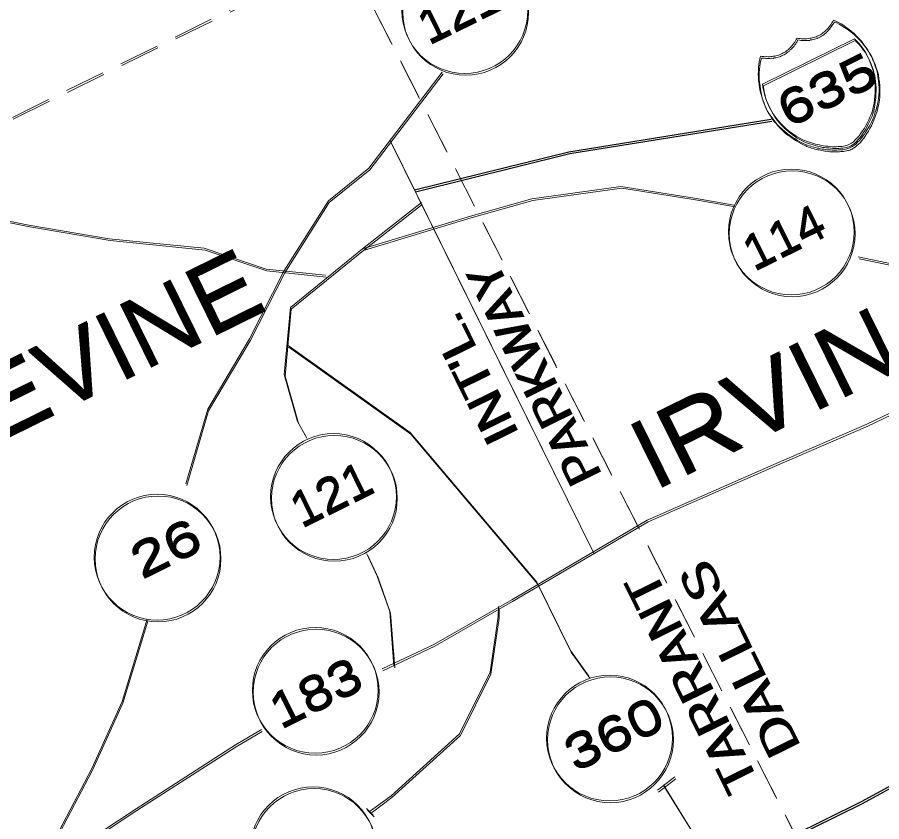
# Model space of a CAD drawing. Extents: x 2356606 to 2371222, y 6973096 to 6982644.
# Drawn here: x 2357309.1 to 2357437.7, y 6973747.7 to 6973867.4 of the extents above; entities that cross this region are included whole.
import ezdxf

# ---------------------------------------------------------------- set-up
doc = ezdxf.new("R2010")
doc.units = 0
doc.header["$LTSCALE"] = 2
doc.linetypes.add('MEDIUM_DASHED', pattern=[4.5, 3, -1.5])
doc.layers.add('62', color=7, linetype='Continuous', lineweight=13)
doc.layers.add('63', color=7, linetype='Continuous', lineweight=13)

msp = doc.modelspace()

# ---------------------------------------------------------------- linework, layer by layer
at = {"layer": '62', "linetype": 'MEDIUM_DASHED'}
for p, q in [((2357443, 6973918.637), (2357041.025, 6973720.25)), ((2357358.049, 6973876.711), (2357485.75, 6973626.399))]:
    msp.add_line(p, q, dxfattribs=at)
at = {"layer": '62'}
for p, q in [((2357394.922, 6973787.559), (2357364.687, 6973848.822)), ((2357410.008, 6973840.223), (2357415.92, 6973839.177)), ((2357360.597, 6973832.702), (2357369.36, 6973839.56)), ((2357456.191, 6973826.984), (2357434.377, 6973831.474)), ((2357346.242, 6973829.655), (2357355.071, 6973828.746)), ((2357337.561, 6973808.811), (2357334.311, 6973797.696)), ((2357350.935, 6973806.979), (2357352.173, 6973804.778)), ((2357362.79, 6973783.975), (2357361.238, 6973787.274)), ((2357386.516, 6973783.085), (2357391.537, 6973772.916)), ((2357380.793, 6973777.951), (2357380.822, 6973779.421)), ((2357324.805, 6973765.304), (2357328.532, 6973777.531)), ((2357371.211, 6973773.776), (2357363.494, 6973770.143)), ((2357391.537, 6973772.916), (2357394.271, 6973769.048)), ((2357341.679, 6973758.824), (2357345.543, 6973761.108)), ((2357404.5, 6973752.087), (2357407.087, 6973754.067)), ((2357411.935, 6973742.308), (2357405.378, 6973752.897)), ((2357364.834, 6973751.259), (2357361.935, 6973749.099)), ((2357361.191, 6973749.385), (2357362.192, 6973748.374)), ((2357361.652, 6973748.908), (2357361.935, 6973749.099))]:
    msp.add_line(p, q, dxfattribs=at)
for points in [[(2357426.144, 6973863.972), (2357426.353, 6973863.95), (2357426.574, 6973863.959), (2357426.746, 6973863.968), (2357426.989, 6973863.987), (2357427.16, 6973864.047), (2357427.361, 6973864.046), (2357427.532, 6973864.106), (2357427.734, 6973864.154), (2357427.914, 6973864.195), (2357428.108, 6973864.264), (2357428.269, 6973864.344), (2357428.448, 6973864.432), (2357428.61, 6973864.511), (2357428.793, 6973864.602), (2357428.966, 6973864.711), (2357429.106, 6973864.831), (2357429.228, 6973864.941), (2357429.398, 6973865.052), (2357429.54, 6973865.222), (2357429.691, 6973865.321), (2357429.833, 6973865.491), (2357429.964, 6973865.632), (2357430.085, 6973865.792), (2357430.219, 6973865.983), (2357430.321, 6973866.133), (2357430.452, 6973866.325), (2357430.584, 6973866.513), (2357430.685, 6973866.715), (2357431.056, 6973866.57), (2357431.428, 6973866.379), (2357431.808, 6973866.165), (2357432.21, 6973865.911), (2357432.592, 6973865.648), (2357432.982, 6973865.365), (2357433.384, 6973865.061), (2357433.745, 6973864.737), (2357434.135, 6973864.352), (2357434.484, 6973863.999), (2357434.835, 6973863.593), (2357435.165, 6973863.178), (2357435.476, 6973862.756), (2357435.783, 6973862.332), (2357436.023, 6973861.896), (2357436.293, 6973861.453), (2357436.501, 6973860.927), (2357436.741, 6973860.396), (2357436.898, 6973859.871), (2357437.097, 6973859.367), (2357437.236, 6973858.833), (2357437.312, 6973858.268), (2357437.392, 6973857.754), (2357437.459, 6973857.211), (2357437.475, 6973856.667), (2357437.462, 6973856.134), (2357437.449, 6973855.599), (2357437.387, 6973855.066), (2357437.294, 6973854.494), (2357437.179, 6973853.96), (2357437.037, 6973853.437), (2357436.862, 6973852.875), (2357436.732, 6973852.484), (2357436.578, 6973852.082), (2357436.384, 6973851.661), (2357436.201, 6973851.269), (2357435.987, 6973850.885), (2357435.764, 6973850.476), (2357435.52, 6973850.104), (2357435.296, 6973849.743), (2357435.074, 6973849.435), (2357434.81, 6973849.102), (2357434.559, 6973848.801), (2357434.284, 6973848.541), (2357434.043, 6973848.32), (2357433.799, 6973848.101), (2357433.535, 6973847.921), (2357433.295, 6973847.801)], [(2357433.295, 6973847.801), (2357433.132, 6973847.721), (2357432.99, 6973847.652), (2357432.81, 6973847.61), (2357432.659, 6973847.563), (2357432.477, 6973847.525), (2357432.296, 6973847.484), (2357432.064, 6973847.445), (2357431.851, 6973847.416), (2357431.653, 6973847.419), (2357431.43, 6973847.409), (2357431.189, 6973847.388), (2357430.969, 6973847.38), (2357430.714, 6973847.382), (2357430.513, 6973847.383), (2357430.253, 6973847.405), (2357430, 6973847.406), (2357429.762, 6973847.437), (2357429.49, 6973847.477), (2357429.248, 6973847.511), (2357429.005, 6973847.542), (2357428.757, 6973847.593), (2357428.493, 6973847.666), (2357428.253, 6973847.696), (2357428.02, 6973847.758), (2357427.77, 6973847.808), (2357427.54, 6973847.872), (2357427.297, 6973847.952), (2357427.075, 6973848.044), (2357426.825, 6973848.096), (2357426.614, 6973848.166), (2357426.434, 6973848.278), (2357426.184, 6973848.382), (2357425.781, 6973848.583), (2357425.339, 6973848.82), (2357424.927, 6973849.093), (2357424.536, 6973849.327), (2357424.143, 6973849.612), (2357423.733, 6973849.886), (2357423.382, 6973850.191), (2357423.012, 6973850.534), (2357422.649, 6973850.857), (2357422.32, 6973851.218), (2357422.012, 6973851.594), (2357421.7, 6973851.968), (2357421.402, 6973852.372), (2357421.122, 6973852.786), (2357420.842, 6973853.25), (2357420.612, 6973853.715), (2357420.403, 6973854.189), (2357420.225, 6973854.653), (2357420.057, 6973855.147), (2357419.909, 6973855.651), (2357419.78, 6973856.165), (2357419.671, 6973856.688), (2357419.624, 6973857.19), (2357419.536, 6973857.726), (2357419.522, 6973858.22), (2357419.502, 6973858.712), (2357419.516, 6973859.195), (2357419.538, 6973859.657), (2357419.6, 6973860.14), (2357419.644, 6973860.562), (2357419.737, 6973860.984), (2357419.83, 6973861.356), (2357420.049, 6973861.314), (2357420.303, 6973861.315), (2357420.513, 6973861.292), (2357420.713, 6973861.294), (2357420.944, 6973861.281), (2357421.147, 6973861.281), (2357421.358, 6973861.309), (2357421.56, 6973861.308), (2357421.732, 6973861.366), (2357421.953, 6973861.375), (2357422.123, 6973861.437), (2357422.324, 6973861.485), (2357422.525, 6973861.535), (2357422.677, 6973861.583), (2357422.838, 6973861.664), (2357423.041, 6973861.764), (2357423.202, 6973861.843), (2357423.364, 6973861.922), (2357423.535, 6973862.033), (2357423.679, 6973862.153), (2357423.82, 6973862.274), (2357423.99, 6973862.38), (2357424.131, 6973862.551), (2357424.282, 6973862.652), (2357424.404, 6973862.812), (2357424.538, 6973862.952), (2357424.699, 6973863.132), (2357424.81, 6973863.314), (2357424.931, 6973863.474), (2357425.045, 6973863.655), (2357425.156, 6973863.837), (2357425.276, 6973864.045), (2357425.497, 6973864.005), (2357425.708, 6973863.983), (2357425.939, 6973863.971), (2357426.144, 6973863.972)], [(2357348.897, 6973829.361), (2357355.513, 6973839.852), (2357361.543, 6973844.711), (2357372.468, 6973858.985)], [(2357371.211, 6973773.776), (2357382.807, 6973780.427), (2357402.976, 6973792.286), (2357422.585, 6973800.911), (2357435.675, 6973806.569), (2357451.93, 6973814.364), (2357460.097, 6973821.157), (2357467.581, 6973832.831), (2357476.49, 6973844.732), (2357479.572, 6973847.534)], [(2357376.643, 6973837.56), (2357385.815, 6973840.13), (2357399.038, 6973841.963), (2357410.008, 6973840.223)], [(2357080.613, 6973783.875), (2357087.936, 6973792.988), (2357099.933, 6973800.965), (2357117.628, 6973801.466), (2357127.853, 6973805.459), (2357143.158, 6973805.208), (2357153.653, 6973805.143), (2357162.234, 6973806.017), (2357173.377, 6973809.108), (2357182.038, 6973812.405), (2357193.134, 6973817.38), (2357205.647, 6973824.158), (2357222.908, 6973830.116), (2357233.839, 6973834.608), (2357246.593, 6973839.121), (2357262.801, 6973839.788), (2357278.346, 6973840.111), (2357292.838, 6973839.837), (2357310.932, 6973836.221), (2357322.909, 6973834.174), (2357337.032, 6973832.764), (2357346.242, 6973829.655)], [(2357349.867, 6973823.943), (2357360.597, 6973832.702), (2357376.643, 6973837.56)], [(2357348.897, 6973829.361), (2357343.762, 6973819.275), (2357337.561, 6973808.811)], [(2357350.935, 6973806.979), (2357348.958, 6973813.986), (2357349.867, 6973823.943)], [(2357386.516, 6973783.085), (2357367.672, 6973805.352), (2357349.514, 6973818.3)], [(2357365.268, 6973770.567), (2357364.637, 6973778.71), (2357362.79, 6973783.975)], [(2357364.834, 6973751.259), (2357375.028, 6973760.503), (2357379.574, 6973769.647), (2357380.793, 6973777.951)], [(2357324.805, 6973765.304), (2357320.284, 6973755.34), (2357311.656, 6973738.864)], [(2357311.295, 6973738.987), (2357326.895, 6973749.32), (2357341.679, 6973758.824)]]:
    msp.add_lwpolyline(points, dxfattribs=at)
msp.add_lwpolyline([(2357433.8, 6973863.961), (2357420.139, 6973857.219), (2357420.158, 6973856.976), (2357420.197, 6973856.695), (2357420.255, 6973856.373), (2357420.363, 6973855.951), (2357420.461, 6973855.495), (2357420.599, 6973855.013), (2357420.828, 6973854.499), (2357421.079, 6973853.945), (2357421.376, 6973853.388), (2357421.674, 6973852.833), (2357422.034, 6973852.308), (2357422.424, 6973851.824), (2357422.825, 6973851.37), (2357423.235, 6973850.945), (2357423.697, 6973850.52), (2357424.158, 6973850.145), (2357424.629, 6973849.801), (2357425.132, 6973849.446), (2357425.673, 6973849.16), (2357426.215, 6973848.875), (2357426.808, 6973848.641), (2357427.401, 6973848.456), (2357427.992, 6973848.27), (2357428.606, 6973848.147), (2357428.908, 6973848.046), (2357429.22, 6973848.024), (2357429.52, 6973847.972), (2357429.853, 6973847.96), (2357430.144, 6973847.927), (2357430.466, 6973847.886), (2357430.767, 6973847.885), (2357431.07, 6973847.882), (2357431.361, 6973847.902), (2357431.633, 6973847.911), (2357431.925, 6973847.929), (2357432.177, 6973847.979), (2357432.431, 6973848.026), (2357432.651, 6973848.086), (2357432.871, 6973848.145), (2357433.074, 6973848.245), (2357433.348, 6973848.405), (2357433.663, 6973848.634), (2357433.935, 6973848.895), (2357434.228, 6973849.216), (2357434.51, 6973849.506), (2357434.775, 6973849.887), (2357435.018, 6973850.258), (2357435.283, 6973850.638), (2357435.526, 6973851.059), (2357435.738, 6973851.491), (2357435.942, 6973851.892), (2357436.113, 6973852.304), (2357436.299, 6973852.696), (2357436.431, 6973853.089), (2357436.554, 6973853.449), (2357436.595, 6973853.772), (2357436.721, 6973854.336), (2357436.771, 6973854.889), (2357436.846, 6973855.402), (2357436.878, 6973855.947), (2357436.9, 6973856.459), (2357436.894, 6973856.932), (2357436.866, 6973857.396), (2357436.808, 6973857.87), (2357436.748, 6973858.339), (2357436.692, 6973858.765), (2357436.573, 6973859.209), (2357436.446, 6973859.621), (2357436.315, 6973860.035), (2357436.167, 6973860.439), (2357435.997, 6973860.832), (2357435.809, 6973861.215), (2357435.542, 6973861.759), (2357435.252, 6973862.243), (2357434.95, 6973862.646), (2357434.692, 6973863.021), (2357434.4, 6973863.355), (2357434.161, 6973863.586), (2357433.962, 6973863.789)], close=True, dxfattribs=at)
at = {"layer": '62', "lineweight": 25}
for points in [[(2357421.398, 6973851.92), (2357391.316, 6973847.084), (2357368.351, 6973841.397)], [(2357505.855, 6973794.281), (2357494.638, 6973787.314), (2357477.945, 6973775.941), (2357457.618, 6973762.773), (2357434.819, 6973750.341), (2357408.769, 6973737.485), (2357380.527, 6973722.566), (2357364.72, 6973713.512)]]:
    msp.add_lwpolyline(points, dxfattribs=at)
at = {"layer": '62'}
for centre in [(2357375.818, 6973868.156), (2357424.414, 6973835.192), (2357356.277, 6973795.807), (2357330.031, 6973786.786), (2357353.563, 6973766.958), (2357397.363, 6973759.862), (2357353.248, 6973743.227)]:
    msp.add_circle(centre, 9.364, dxfattribs=at)
at = {"layer": '63', "linetype": 'MEDIUM_DASHED'}
for p, q in [((2357442.87, 6973918.9), (2357040.895, 6973720.513)), ((2357357.919, 6973876.974), (2357485.62, 6973626.662))]:
    msp.add_line(p, q, dxfattribs=at)
at = {"layer": '63'}
for p, q in [((2357394.792, 6973787.822), (2357364.557, 6973849.085)), ((2357409.878, 6973840.486), (2357415.79, 6973839.44)), ((2357360.467, 6973832.965), (2357369.23, 6973839.823)), ((2357456.061, 6973827.247), (2357434.247, 6973831.737)), ((2357346.112, 6973829.918), (2357354.941, 6973829.009)), ((2357337.431, 6973809.074), (2357334.181, 6973797.959)), ((2357350.805, 6973807.242), (2357352.043, 6973805.041)), ((2357362.66, 6973784.238), (2357361.108, 6973787.537)), ((2357386.386, 6973783.348), (2357391.407, 6973773.179)), ((2357380.663, 6973778.214), (2357380.692, 6973779.684)), ((2357324.675, 6973765.567), (2357328.402, 6973777.794)), ((2357371.081, 6973774.039), (2357363.364, 6973770.406)), ((2357391.407, 6973773.179), (2357394.141, 6973769.311)), ((2357341.549, 6973759.087), (2357345.413, 6973761.371)), ((2357404.37, 6973752.35), (2357406.957, 6973754.33)), ((2357411.805, 6973742.571), (2357405.248, 6973753.16)), ((2357364.704, 6973751.522), (2357361.805, 6973749.362)), ((2357361.061, 6973749.648), (2357362.062, 6973748.637)), ((2357361.522, 6973749.171), (2357361.805, 6973749.362))]:
    msp.add_line(p, q, dxfattribs=at)
for points in [[(2357426.014, 6973864.235), (2357426.223, 6973864.213), (2357426.444, 6973864.222), (2357426.616, 6973864.231), (2357426.859, 6973864.25), (2357427.03, 6973864.31), (2357427.231, 6973864.309), (2357427.402, 6973864.369), (2357427.604, 6973864.417), (2357427.784, 6973864.458), (2357427.978, 6973864.527), (2357428.139, 6973864.607), (2357428.318, 6973864.695), (2357428.48, 6973864.774), (2357428.663, 6973864.865), (2357428.836, 6973864.974), (2357428.976, 6973865.094), (2357429.098, 6973865.204), (2357429.268, 6973865.315), (2357429.41, 6973865.485), (2357429.561, 6973865.584), (2357429.703, 6973865.754), (2357429.834, 6973865.895), (2357429.955, 6973866.055), (2357430.089, 6973866.246), (2357430.191, 6973866.396), (2357430.322, 6973866.588), (2357430.454, 6973866.776), (2357430.555, 6973866.978), (2357430.926, 6973866.833), (2357431.298, 6973866.642), (2357431.678, 6973866.428), (2357432.08, 6973866.174), (2357432.462, 6973865.911), (2357432.852, 6973865.628), (2357433.254, 6973865.324), (2357433.615, 6973865), (2357434.005, 6973864.615), (2357434.354, 6973864.262), (2357434.705, 6973863.856), (2357435.035, 6973863.441), (2357435.346, 6973863.019), (2357435.653, 6973862.595), (2357435.893, 6973862.159), (2357436.163, 6973861.716), (2357436.371, 6973861.19), (2357436.611, 6973860.659), (2357436.768, 6973860.134), (2357436.967, 6973859.63), (2357437.106, 6973859.096), (2357437.182, 6973858.531), (2357437.262, 6973858.017), (2357437.329, 6973857.474), (2357437.345, 6973856.93), (2357437.332, 6973856.397), (2357437.319, 6973855.862), (2357437.257, 6973855.329), (2357437.164, 6973854.757), (2357437.049, 6973854.223), (2357436.907, 6973853.7), (2357436.732, 6973853.138), (2357436.602, 6973852.747), (2357436.448, 6973852.345), (2357436.254, 6973851.924), (2357436.071, 6973851.532), (2357435.857, 6973851.148), (2357435.634, 6973850.739), (2357435.39, 6973850.367), (2357435.166, 6973850.006), (2357434.944, 6973849.698), (2357434.68, 6973849.365), (2357434.429, 6973849.064), (2357434.154, 6973848.804), (2357433.913, 6973848.583), (2357433.669, 6973848.364), (2357433.405, 6973848.184), (2357433.165, 6973848.064)], [(2357433.165, 6973848.064), (2357433.002, 6973847.984), (2357432.86, 6973847.915), (2357432.68, 6973847.873), (2357432.529, 6973847.826), (2357432.347, 6973847.788), (2357432.166, 6973847.747), (2357431.934, 6973847.708), (2357431.721, 6973847.679), (2357431.523, 6973847.682), (2357431.3, 6973847.672), (2357431.059, 6973847.651), (2357430.839, 6973847.643), (2357430.584, 6973847.645), (2357430.383, 6973847.646), (2357430.123, 6973847.668), (2357429.87, 6973847.669), (2357429.632, 6973847.7), (2357429.36, 6973847.74), (2357429.118, 6973847.774), (2357428.875, 6973847.805), (2357428.627, 6973847.856), (2357428.363, 6973847.929), (2357428.123, 6973847.959), (2357427.89, 6973848.021), (2357427.64, 6973848.071), (2357427.41, 6973848.135), (2357427.167, 6973848.215), (2357426.945, 6973848.307), (2357426.695, 6973848.359), (2357426.484, 6973848.429), (2357426.304, 6973848.541), (2357426.054, 6973848.645), (2357425.651, 6973848.846), (2357425.209, 6973849.083), (2357424.797, 6973849.356), (2357424.406, 6973849.59), (2357424.013, 6973849.875), (2357423.603, 6973850.149), (2357423.252, 6973850.454), (2357422.882, 6973850.797), (2357422.519, 6973851.12), (2357422.19, 6973851.481), (2357421.882, 6973851.857), (2357421.57, 6973852.231), (2357421.272, 6973852.635), (2357420.992, 6973853.049), (2357420.712, 6973853.513), (2357420.482, 6973853.978), (2357420.273, 6973854.452), (2357420.095, 6973854.916), (2357419.927, 6973855.41), (2357419.779, 6973855.914), (2357419.65, 6973856.428), (2357419.541, 6973856.951), (2357419.494, 6973857.453), (2357419.406, 6973857.989), (2357419.392, 6973858.483), (2357419.372, 6973858.975), (2357419.386, 6973859.458), (2357419.408, 6973859.92), (2357419.47, 6973860.403), (2357419.514, 6973860.825), (2357419.607, 6973861.247), (2357419.7, 6973861.619), (2357419.919, 6973861.577), (2357420.173, 6973861.578), (2357420.383, 6973861.555), (2357420.583, 6973861.557), (2357420.814, 6973861.544), (2357421.017, 6973861.544), (2357421.228, 6973861.572), (2357421.43, 6973861.571), (2357421.602, 6973861.629), (2357421.823, 6973861.638), (2357421.993, 6973861.7), (2357422.194, 6973861.748), (2357422.395, 6973861.798), (2357422.547, 6973861.846), (2357422.708, 6973861.927), (2357422.911, 6973862.027), (2357423.072, 6973862.106), (2357423.234, 6973862.185), (2357423.405, 6973862.296), (2357423.549, 6973862.416), (2357423.69, 6973862.537), (2357423.86, 6973862.643), (2357424.001, 6973862.814), (2357424.152, 6973862.915), (2357424.274, 6973863.075), (2357424.408, 6973863.215), (2357424.569, 6973863.395), (2357424.68, 6973863.577), (2357424.801, 6973863.737), (2357424.915, 6973863.918), (2357425.026, 6973864.1), (2357425.146, 6973864.308), (2357425.367, 6973864.268), (2357425.578, 6973864.246), (2357425.809, 6973864.234), (2357426.014, 6973864.235)], [(2357348.767, 6973829.624), (2357355.383, 6973840.115), (2357361.413, 6973844.974), (2357372.338, 6973859.248)], [(2357371.081, 6973774.039), (2357382.677, 6973780.69), (2357402.846, 6973792.549), (2357422.455, 6973801.174), (2357435.545, 6973806.832), (2357451.8, 6973814.627), (2357459.967, 6973821.42), (2357467.451, 6973833.094), (2357476.36, 6973844.995), (2357479.442, 6973847.797)], [(2357376.513, 6973837.823), (2357385.685, 6973840.393), (2357398.908, 6973842.226), (2357409.878, 6973840.486)], [(2357080.483, 6973784.138), (2357087.806, 6973793.251), (2357099.803, 6973801.228), (2357117.498, 6973801.729), (2357127.723, 6973805.722), (2357143.028, 6973805.471), (2357153.523, 6973805.406), (2357162.104, 6973806.28), (2357173.247, 6973809.371), (2357181.908, 6973812.668), (2357193.004, 6973817.643), (2357205.517, 6973824.421), (2357222.778, 6973830.379), (2357233.709, 6973834.871), (2357246.463, 6973839.384), (2357262.671, 6973840.051), (2357278.216, 6973840.374), (2357292.708, 6973840.1), (2357310.802, 6973836.484), (2357322.779, 6973834.437), (2357336.902, 6973833.027), (2357346.112, 6973829.918)], [(2357349.737, 6973824.206), (2357360.467, 6973832.965), (2357376.513, 6973837.823)], [(2357348.767, 6973829.624), (2357343.632, 6973819.538), (2357337.431, 6973809.074)], [(2357350.805, 6973807.242), (2357348.828, 6973814.249), (2357349.737, 6973824.206)], [(2357386.386, 6973783.348), (2357367.542, 6973805.615), (2357349.384, 6973818.563)], [(2357365.138, 6973770.83), (2357364.507, 6973778.973), (2357362.66, 6973784.238)], [(2357364.704, 6973751.522), (2357374.898, 6973760.766), (2357379.444, 6973769.91), (2357380.663, 6973778.214)], [(2357324.675, 6973765.567), (2357320.154, 6973755.603), (2357311.526, 6973739.127)], [(2357311.165, 6973739.25), (2357326.765, 6973749.583), (2357341.549, 6973759.087)]]:
    msp.add_lwpolyline(points, dxfattribs=at)
msp.add_lwpolyline([(2357433.67, 6973864.224), (2357420.009, 6973857.482), (2357420.028, 6973857.239), (2357420.067, 6973856.958), (2357420.125, 6973856.636), (2357420.233, 6973856.214), (2357420.331, 6973855.758), (2357420.469, 6973855.276), (2357420.698, 6973854.762), (2357420.949, 6973854.208), (2357421.246, 6973853.651), (2357421.544, 6973853.096), (2357421.904, 6973852.571), (2357422.294, 6973852.087), (2357422.695, 6973851.633), (2357423.105, 6973851.208), (2357423.567, 6973850.783), (2357424.028, 6973850.408), (2357424.499, 6973850.064), (2357425.002, 6973849.709), (2357425.543, 6973849.423), (2357426.085, 6973849.138), (2357426.678, 6973848.904), (2357427.271, 6973848.719), (2357427.862, 6973848.533), (2357428.476, 6973848.41), (2357428.778, 6973848.309), (2357429.09, 6973848.287), (2357429.39, 6973848.235), (2357429.723, 6973848.223), (2357430.014, 6973848.19), (2357430.336, 6973848.149), (2357430.637, 6973848.148), (2357430.94, 6973848.145), (2357431.231, 6973848.165), (2357431.503, 6973848.174), (2357431.795, 6973848.192), (2357432.047, 6973848.242), (2357432.301, 6973848.289), (2357432.521, 6973848.349), (2357432.741, 6973848.408), (2357432.944, 6973848.508), (2357433.218, 6973848.668), (2357433.533, 6973848.897), (2357433.805, 6973849.158), (2357434.098, 6973849.479), (2357434.38, 6973849.769), (2357434.645, 6973850.15), (2357434.888, 6973850.521), (2357435.153, 6973850.901), (2357435.396, 6973851.322), (2357435.608, 6973851.754), (2357435.812, 6973852.155), (2357435.983, 6973852.567), (2357436.169, 6973852.959), (2357436.301, 6973853.352), (2357436.424, 6973853.712), (2357436.465, 6973854.035), (2357436.591, 6973854.599), (2357436.641, 6973855.152), (2357436.716, 6973855.665), (2357436.748, 6973856.21), (2357436.77, 6973856.722), (2357436.764, 6973857.195), (2357436.736, 6973857.659), (2357436.678, 6973858.133), (2357436.618, 6973858.602), (2357436.562, 6973859.028), (2357436.443, 6973859.472), (2357436.316, 6973859.884), (2357436.185, 6973860.298), (2357436.037, 6973860.702), (2357435.867, 6973861.095), (2357435.679, 6973861.478), (2357435.412, 6973862.022), (2357435.122, 6973862.506), (2357434.82, 6973862.909), (2357434.562, 6973863.284), (2357434.27, 6973863.618), (2357434.031, 6973863.849), (2357433.832, 6973864.052)], close=True, dxfattribs=at)
at = {"layer": '63', "lineweight": 25}
for points in [[(2357421.268, 6973852.183), (2357391.186, 6973847.347), (2357368.221, 6973841.66)], [(2357505.725, 6973794.544), (2357494.508, 6973787.577), (2357477.815, 6973776.204), (2357457.488, 6973763.036), (2357434.689, 6973750.604), (2357408.639, 6973737.748), (2357380.397, 6973722.829), (2357364.59, 6973713.775)]]:
    msp.add_lwpolyline(points, dxfattribs=at)
at = {"layer": '63'}
for centre in [(2357375.688, 6973868.419), (2357424.284, 6973835.455), (2357356.147, 6973796.07), (2357329.901, 6973787.049), (2357353.433, 6973767.222), (2357397.233, 6973760.125), (2357353.118, 6973743.49)]:
    msp.add_circle(centre, 9.364, dxfattribs=at)

# ---------------------------------------------------------------- texts
at = {"layer": '62'}
for s, height, rotation, width, p in [('121', 5.099, 26.268, 1.1, (2357370.364, 6973863.145)), ('635', 5.099, 26.268, 1.35, (2357423.899, 6973850.821)), ('114', 5.099, 26.268, 1.1, (2357418.759, 6973829.463)), ('GRAPEVINE', 10.21, 26.268, 1.1, (2357268.029, 6973785.16)), ('PARKWAY', 5.099, 116.268, 1.05, (2357396.22, 6973799.27)), ('IRVING', 10.21, 26.268, 1.15, (2357403.785, 6973796.752)), ("INT'L.", 5.099, 116.268, 1.15, (2357383.906, 6973805.361)), ('121', 5.099, 26.268, 1.1, (2357351.408, 6973791.23)), ('26', 5.099, 26.268, 1.4, (2357327.617, 6973783.604)), ('DALLAS', 5.099, 116.268, 1.2, (2357425.839, 6973758.781)), ('TARRANT', 5.099, 116.268, 1.1, (2357419.601, 6973753.47)), ('183', 5.099, 26.268, 1.25, (2357348.293, 6973761.287)), ('360', 5.099, 26.268, 1.35, (2357392.178, 6973754.939)), ('GRAND', 10.21, 26.268, 1.05, (2357435.168, 6973727.828))]:
    msp.add_text(s, height=height, rotation=rotation, dxfattribs=dict(at, width=width)).set_placement(p)
at = {"layer": '63'}
for s, height, rotation, width, p in [('121', 5.099, 26.268, 1.1, (2357370.234, 6973863.409)), ('635', 5.099, 26.268, 1.35, (2357423.769, 6973851.085)), ('114', 5.099, 26.268, 1.1, (2357418.629, 6973829.727)), ('GRAPEVINE', 10.21, 26.268, 1.1, (2357267.899, 6973785.424)), ('PARKWAY', 5.099, 116.268, 1.05, (2357396.09, 6973799.534)), ('IRVING', 10.21, 26.268, 1.15, (2357403.655, 6973797.016)), ("INT'L.", 5.099, 116.268, 1.15, (2357383.776, 6973805.625)), ('121', 5.099, 26.268, 1.1, (2357351.278, 6973791.494)), ('26', 5.099, 26.268, 1.4, (2357327.487, 6973783.868)), ('DALLAS', 5.099, 116.268, 1.2, (2357425.709, 6973759.045)), ('TARRANT', 5.099, 116.268, 1.1, (2357419.471, 6973753.734)), ('183', 5.099, 26.268, 1.25, (2357348.163, 6973761.551)), ('360', 5.099, 26.268, 1.35, (2357392.048, 6973755.203)), ('GRAND', 10.21, 26.268, 1.05, (2357435.038, 6973728.092))]:
    msp.add_text(s, height=height, rotation=rotation, dxfattribs=dict(at, width=width)).set_placement(p)

doc.saveas('drawing.dxf')
